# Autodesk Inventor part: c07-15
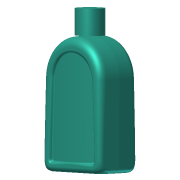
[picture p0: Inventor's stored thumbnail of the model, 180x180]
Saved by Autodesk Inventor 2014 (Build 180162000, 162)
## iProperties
Created: 2010-12
Part Number: c07-15
Material: Generic
Document SubType Name: Modeling
Designer: Beta-8540w
Density: 1 g/cm^3
Appearance: Smooth - Aqua
Author: Beta-8540w
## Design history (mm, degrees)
sketch "Sketch1"
  geometry: L1 (-25, 0)-(25, 0); L2 (25, 0)-(25, 80); L3 (25, 80)-(-25, 80); L4 (-25, 80)-(-25, 0); 2 further points
  constraints: 8 end point, 2 parallel, 1 coincident, 1 horizontal, 1 midpoint, 1 perpendicular
  dimensions: "d0" = 50 distance of L3.end L2.end; "d1" = 80 distance of L2.end L1.end
extrude "Extrusion1" new body sketch "Sketch1" distance "d2" = 15; taper "d3" = 0 deg
feature "FaceDraft1" dims angle "d4" = -2 deg
fillet "Fillet1"
fillet "Fillet2" dims "d5" = 8, "d6" = 8, "d7" = 8, "d8" = 8, "d9" = 8, "d10" = 8, "d11" = 3, "d12" = 3, "d13" = 3, "d14" = 6, "d15" = 5
sketch "Sketch2"
  geometry: L1 (5.522, 12)-(38.474, 12) reference; L2 (0, 0)-(43.996, 0) reference; L3 (41.757, 6.83)-(41.995, 0); L4 (41.925, 2)-(2.071, 2); L5 (2.001, 0)-(2.24, 6.83); L6 (5.522, 10)-(38.474, 10); A1 r 5.284 centre (38.474, 6.716) between (43.755, 6.9) and (38.474, 12) reference; A2 r 5.284 centre (5.522, 6.716) between (5.522, 12) and (0.241, 6.9) reference; A3 r 3.284 centre (38.474, 6.716) between (41.757, 6.83) and (38.474, 10); A4 r 3.284 centre (5.522, 6.716) between (5.522, 10) and (2.24, 6.83); 1 further point
  constraints: 8 end point, 4 point on circle, 4 point on line, 2 centre point, 1 other
  dimensions: "d16" = 2 radial gap between concentric circles of A2 A4
extrude "Extrusion2" cut sketch "Sketch2" distance "d17" = 3; taper "d18" = 0 deg
feature "FaceDraft2" dims angle "d19" = 15 deg
sketch "Sketch3" dims "d20" = 2.5
  geometry: L1 (16.476, 3)-(-16.476, 3) reference; L2 (16.476, 5.5)-(-16.476, 5.5); 9 further points
  constraints: 2 end point, 2 parallel, 1 horizontal alignment, 19 other
extrude "Extrusion3" cut sketch "Sketch3" distance "d21" = 3; taper "d22" = 0 deg
feature "FaceDraft3" dims angle "d23" = 10 deg
workplane "Work Plane1"
sketch "Sketch4"
  geometry: L1 (41.1, -1.222)-(41.476, -12) reference; L2 (41.476, -12)-(-8.524, -12) reference; L3 (-8.524, -12)-(-8.147, -1.222) reference; L4 (-3.776, 3)-(-1.272, 3) reference; L5 (-0.743, 0)-(33.695, 0) reference; L6 (34.225, 3)-(36.728, 3) reference; L7 (-11.024, -1.804)-(43.976, -1.804); A1 r 90 centre (16.476, -87.5) between (43.976, -1.804) and (-11.024, -1.804); 2 further points
  constraints: 2 end point, 2 point on circle, 1 centre point, 1 midpoint, 1 parallel, 1 vertical alignment, 4 other
  dimensions: "d25" = 90 radius of A1; "d26" = 14.5 distance edge to line of A1 L2; "d27" = 55 distance of L7.start L7.end
extrude_surface "ExtrusionSrf1" sketch "Sketch4" dims "d28" = 86, "d29" = 0
feature "Replace Face1"
fillet "Fillet3" dims "d34" = 1, "d35" = 2
mirror "Mirror1"
fillet "Fillet4" dims "d36" = 20
workplane "Work Plane3"
sketch "Sketch6"
  geometry: C1 r 9 at (0, 0); 1 further point
  constraints: 1 centre point, 1 coincident
  dimensions: "d38" = 18 diameter of C1
extrude "Top Boss" join sketch "Sketch6" distance "d39" = 16; taper "d40" = 0 deg
body "Solid1"
body "Srf1"
node "Project Cut Edges1"
